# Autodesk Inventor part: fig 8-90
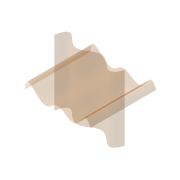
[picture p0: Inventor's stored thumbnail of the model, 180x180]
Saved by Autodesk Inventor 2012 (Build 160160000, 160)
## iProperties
Shininess: 64.0
Length Units: 11269
Angle Units: 11279
Time Units: 11290
Mass Units: 11283
Length Display Precision: 3
Angle Display Precision: 2
Compacted: True
Part Number: fig 8-90
Document SubType Name: Modeling
Created: 2003-08
Designer: Owner
Manufacturer: Standard
Standards Organization: Custom
Density: 1 g/cm^3
Material: Default
Density: 0.0
Volumn: 0.0
Area: 0.0
PropertySet Name: Model Information
Control State: 0
Master: False
Checked Out: False
Author: Owner
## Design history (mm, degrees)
sketch "Sketch1"
  geometry: 7 further points
  constraints: 7 other
  dimensions: "d0" = 80 horizontal distance of point (40, 1.742) point (-40, -4.065); "d1" = 40 horizontal distance of point (0, 0) point (-40, -4.065)
extrude_surface "ExtrusionSrf1" sketch "Sketch1" dims "d2" = 80, "d3" = 0
sketch "Sketch2"
  geometry: L1 (40, 0)-(40, -40) reference; L2 (-40, 0)-(-40, -40) reference; 7 further points
  constraints: 2 point on line, 7 other
extrude_surface "ExtrusionSrf2" sketch "Sketch2" dims "d4" = 80, "d5" = 0
sketch "Sketch3"
  geometry: 2 further points
  constraints: 4 other
sketch "Sketch4"
  geometry: L1 (52.956, 12.425)-(-10.974, 12.425); A1 r 27.841 centre (-10.974, -15.416) between (-10.974, 12.425) and (-7.259, -43.008)
  constraints: 2 end point, 2 point on circle, 1 centre point, 1 horizontal, 1 tangent
body "Srf1"
body "Srf2"
